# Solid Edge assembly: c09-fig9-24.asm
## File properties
Author: Robert a Rhodes jr
Template: Normal.asm
Last saved by: Cadcim
Revision: 6
Application: Solid Edge
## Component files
plate.par
bolt.par
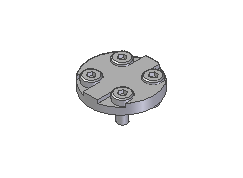
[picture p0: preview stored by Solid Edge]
